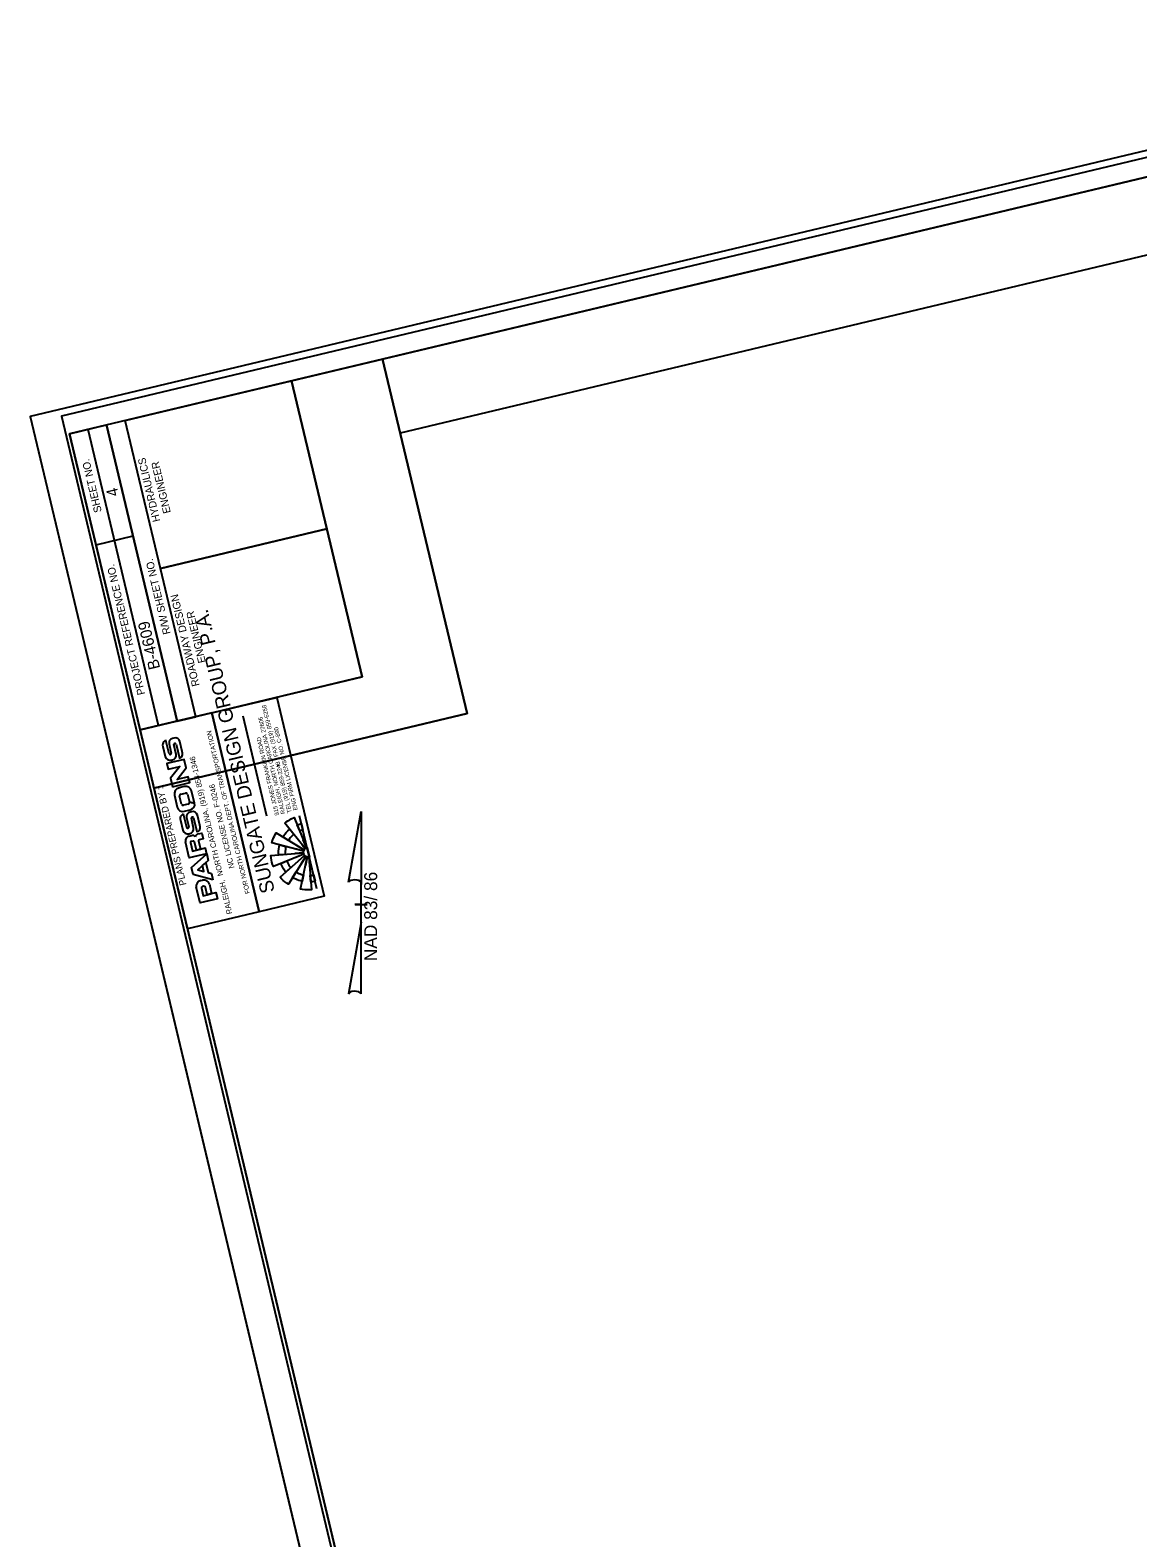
# Model space of a CAD drawing. Extents: x 1735488 to 1736943, y 699358 to 701250.
# Drawn here: x 1735488 to 1736215, y 700259 to 701250 of the extents above; entities that cross this region are included whole.
import ezdxf

# ---------------------------------------------------------------- set-up
doc = ezdxf.new("R2010")
doc.units = 0
for name, color, linetype in [('Default', 7, 'Continuous'), ('Old_Level_2', 7, 'Continuous'), ('Prop North Arrow NAD83 for Plan Sheets CELL', 7, 'Continuous'), ('Sheet Clip Boundary CELL', 7, 'Continuous'), ('Sheet Cutting Line CELL', 7, 'Continuous'), ('Sheet Data Field CELL', 7, 'Continuous'), ('Sheet Layout Plan Border', 7, 'Continuous'), ('Sheet Plan CELL', 7, 'Continuous'), ('Sheet Plan Layout CELL', 7, 'Continuous'), ('Sheet Plot Border Inside CELL', 7, 'Continuous'), ('Sheet Plot Border Outside CELL', 7, 'Continuous')]:
    doc.layers.add(name, color=color, linetype=linetype)

msp = doc.modelspace()

# ---------------------------------------------------------------- linework, layer by layer
at = {"layer": 'Default'}
for p, q in [((1735643.19, 700733.5), (1735627.54, 700799.17)), ((1735676.1, 700685.63), (1735664.66, 700733.63)), ((1735668.39, 700712.12), (1735664.87, 700716.53)), ((1735666.35, 700714.67), (1735668.39, 700712.12)), ((1735669.2, 700712.59), (1735667.09, 700717.83)), ((1735655.66, 700713.45), (1735655.66, 700713.45)), ((1735667.2, 700709.35), (1735661.58, 700708.86)), ((1735667.3, 700710.43), (1735661.83, 700711.86)), ((1735667.42, 700708.44), (1735662.18, 700706.34)), ((1735662.83, 700714.23), (1735667.66, 700711.29)), ((1735667.99, 700707.52), (1735663.75, 700703.78)), ((1735665.72, 700702.12), (1735668.7, 700706.92)), ((1735669.73, 700706.51), (1735668.58, 700700.98)), ((1735670.66, 700706.45), (1735671.14, 700700.83)), ((1735658.96, 700699.63), (1735658.96, 700699.63)), ((1735668.88, 700702.49), (1735668.88, 700702.49)), ((1735671.9, 700692.25), (1735671.9, 700692.25))]:
    msp.add_line(p, q, dxfattribs=at)
for points in [[(1735638.12, 700670.55), (1735606.96, 700801.29), (1735649.78, 700811.49), (1735680.94, 700680.75)], [(1735653.73, 700719.77), (1735654.35, 700720.73), (1735655.06, 700721.69), (1735655.83, 700722.6), (1735656.96, 700723.77), (1735658.22, 700724.86), (1735660.92, 700721.49), (1735660.09, 700720.78), (1735659.19, 700719.88), (1735658.58, 700719.17), (1735658.07, 700718.49), (1735657.42, 700717.52)], [(1735668.41, 700712.12), (1735654.99, 700728.92), (1735655.89, 700729.6), (1735656.97, 700730.35), (1735658.24, 700731.11), (1735659.26, 700731.66), (1735661.2, 700732.54), (1735669.2, 700712.59)], [(1735663.13, 700727.72), (1735664.53, 700728.22), (1735665.82, 700728.58), (1735666.86, 700724.38), (1735665.8, 700724.09), (1735664.74, 700723.71)], [(1735667.3, 700710.43), (1735646.5, 700715.85), (1735646.96, 700717.41), (1735647.63, 700719.18), (1735648.14, 700720.32), (1735648.69, 700721.4), (1735649.31, 700722.47), (1735667.66, 700711.29)], [(1735650.96, 700707.93), (1735650.89, 700709.13), (1735650.9, 700710.49), (1735651.02, 700711.88), (1735651.21, 700713.16), (1735651.51, 700714.54), (1735655.7, 700713.45), (1735655.52, 700712.67), (1735655.34, 700711.65), (1735655.22, 700710.22), (1735655.21, 700709.23), (1735655.27, 700708.31)], [(1735667.42, 700708.44), (1735647.47, 700700.45), (1735646.99, 700701.74), (1735646.55, 700703.21), (1735646.24, 700704.47), (1735645.96, 700706.03), (1735645.79, 700707.48), (1735667.2, 700709.35)], [(1735668.7, 700706.92), (1735657.36, 700688.66), (1735656.2, 700689.43), (1735655.01, 700690.32), (1735653.93, 700691.23), (1735652.84, 700692.27), (1735651.87, 700693.31), (1735667.99, 700707.52)], [(1735670.66, 700706.45), (1735672.53, 700685.05), (1735671.22, 700684.97), (1735669.29, 700684.98), (1735668.09, 700685.06), (1735666.54, 700685.25), (1735665.36, 700685.47), (1735669.73, 700706.51)], [(1735671.12, 700706.53), (1735670.88, 700706.48), (1735670.66, 700706.45), (1735670.15, 700706.45), (1735669.73, 700706.51), (1735669.41, 700706.59), (1735669.12, 700706.7), (1735668.88, 700706.82), (1735668.7, 700706.92), (1735668.31, 700707.2), (1735667.99, 700707.52), (1735667.8, 700707.75), (1735667.63, 700708.02), (1735667.5, 700708.26), (1735667.42, 700708.44), (1735667.28, 700708.9), (1735667.2, 700709.35), (1735667.19, 700709.63), (1735667.2, 700709.87), (1735667.23, 700710.14), (1735667.3, 700710.43), (1735667.44, 700710.87), (1735667.66, 700711.29), (1735667.8, 700711.5), (1735667.98, 700711.73), (1735668.15, 700711.91), (1735668.39, 700712.12), (1735668.8, 700712.4), (1735669.2, 700712.59), (1735669.42, 700712.67), (1735669.64, 700712.73)], [(1735655.76, 700696.73), (1735655.09, 700697.53), (1735654.19, 700698.77), (1735653.35, 700700.13), (1735652.71, 700701.39), (1735652.28, 700702.38), (1735656.3, 700703.99), (1735656.71, 700703.05), (1735657.16, 700702.18), (1735657.7, 700701.3), (1735658.34, 700700.39), (1735659, 700699.59)], [(1735666.42, 700690.54), (1735665.23, 700690.83), (1735664.29, 700691.11), (1735663.18, 700691.51), (1735662.19, 700691.94), (1735661.2, 700692.43), (1735660.1, 700693.07), (1735662.38, 700696.74), (1735663.3, 700696.21), (1735664.11, 700695.81), (1735664.96, 700695.46), (1735665.9, 700695.13), (1735666.65, 700694.92), (1735667.3, 700694.77)], [(1735674.9, 700690.67), (1735674.07, 700690.49), (1735673.09, 700690.33), (1735672.08, 700690.21), (1735671.7, 700694.52), (1735672.43, 700694.6), (1735673.16, 700694.72), (1735673.89, 700694.88)]]:
    msp.add_lwpolyline(points, close=True, dxfattribs=at)
for start, end in [(103.40586, 283.40586), (283.40586, 103.40586)]:
    msp.add_arc((1735650.54, 700766.89), 0.138, start, end, dxfattribs=at)
at = {"layer": 'Old_Level_2'}
for p, q in [((1735606.96, 700801.29), (1735559.86, 700790.06)), ((1735606.96, 700801.29), (1735638.12, 700670.55)), ((1735591.02, 700659.32), (1735559.86, 700790.06)), ((1735582.13, 700784.73), (1735581.24, 700784.52)), ((1735574.81, 700779.17), (1735576.35, 700772.7)), ((1735579, 700774.44), (1735576.91, 700783.2)), ((1735578.92, 700781.03), (1735580.41, 700774.77)), ((1735583.52, 700773.98), (1735582.14, 700780.4)), ((1735587.63, 700775.83), (1735586.04, 700782.51)), ((1735580.62, 700770.27), (1735581.07, 700770.38)), ((1735582.43, 700747.19), (1735584.32, 700739.27)), ((1735588.88, 700752.8), (1735585.67, 700752.03)), ((1735587.03, 700741.37), (1735585.8, 700746.53)), ((1735586.73, 700747.92), (1735589.63, 700748.61)), ((1735595.73, 700741.85), (1735593.78, 700750.04)), ((1735590.54, 700726.03), (1735588.45, 700734.79)), ((1735591.39, 700741.25), (1735588.49, 700740.55)), ((1735589.03, 700736.62), (1735592.83, 700737.52)), ((1735595.73, 700741.85), (1735592.32, 700742.63)), ((1735593.67, 700736.33), (1735592.77, 700736.11)), ((1735586.34, 700730.77), (1735587.89, 700724.3)), ((1735590.46, 700732.62), (1735591.95, 700726.37)), ((1735595.06, 700725.58), (1735593.67, 700732)), ((1735599.17, 700727.43), (1735597.58, 700734.11)), ((1735592.16, 700721.87), (1735592.61, 700721.98)), ((1735592.2, 700720.36), (1735593.92, 700720.77)), ((1735594.72, 700717.06), (1735593.45, 700716.76)), ((1735599.73, 700691.11), (1735600.84, 700691.37)), ((1735601.56, 700687.35), (1735600.89, 700687.19)), ((1735638.12, 700670.55), (1735591.02, 700659.32))]:
    msp.add_line(p, q, dxfattribs=at)
for points in [[(1735583.55, 700780.74), (1735585.72, 700771.63), (1735585.95, 700771.68)], [(1735591.09, 700747.79), (1735592.32, 700742.63), (1735595.73, 700741.85), (1735593.78, 700750.04)], [(1735595.09, 700732.33), (1735597.26, 700723.23), (1735597.48, 700723.28)], [(1735593.05, 700716.15), (1735594.39, 700710.52), (1735596.92, 700711.12), (1735599.68, 700711.78), (1735602.72, 700712.51), (1735603.62, 700708.75), (1735592.24, 700706.04), (1735589.72, 700716.6)], [(1735597.93, 700721.72), (1735600.39, 700722.31), (1735601.3, 700718.49), (1735598.69, 700717.86), (1735598.37, 700717.27), (1735599.68, 700711.78), (1735596.92, 700711.12), (1735595.63, 700716.54)], [(1735600.2, 700686.14), (1735601.39, 700681.12), (1735604, 700681.74), (1735606.89, 700682.5), (1735609.72, 700683.17), (1735610.68, 700679.13), (1735599.3, 700676.42), (1735596.84, 700686.74)], [(1735605.4, 700688.78), (1735606.89, 700682.5), (1735604, 700681.74), (1735602.84, 700686.62)]]:
    msp.add_lwpolyline(points, dxfattribs=at)
for points in [[(1735581.1, 700752.78), (1735592.48, 700755.49), (1735591.56, 700759.35), (1735584.19, 700757.59), (1735590.15, 700765.27), (1735588.85, 700770.71), (1735577.47, 700767.99), (1735578.36, 700764.28), (1735585.94, 700766.09), (1735579.78, 700758.29)], [(1735607.7, 700691.63), (1735594.83, 700695.18), (1735593.74, 700699.72), (1735603.65, 700708.63), (1735604.67, 700704.36), (1735597.74, 700698.13), (1735601.86, 700697), (1735600.91, 700700.99), (1735602.98, 700702.86), (1735604.54, 700696.33), (1735606.72, 700695.76)]]:
    msp.add_lwpolyline(points, close=True, dxfattribs=at)
for centre, major_axis, ratio, start_param, end_param in [((1735581.9, 700781.74), (-2.98, -0.71), 0.934072, 4.712389, 6.283185), ((1735582.84, 700781.75), (-3.2, -0.76), 0.934072, 3.141593, 4.712389), ((1735579.64, 700780.32), (-4.84, -1.15), 0.934072, 5.902203, 6.283185), ((1735577.62, 700780.57), (-2.83, -0.67), 0.934072, 4.738699, 5.901866), ((1735579.71, 700774.61), (-0.707, -0.169), 0.934072, 0, 3.141593), ((1735580.38, 700773.3), (3.13, 0.75), 0.934072, 4.712389, 6.260753), ((1735582.85, 700780.57), (-0.707, -0.169), 0.934072, 3.141593, 6.283185), ((1735580.19, 700774.06), (-7.44, -1.77), 0.934072, 2.847261, 3.141593), ((1735579.84, 700773.54), (-3.5, -0.83), 0.934072, 0, 1.570796), ((1735585.43, 700773.84), (2.31, 0.55), 0.934072, 4.712389, 5.988639), ((1735586.6, 700748.18), (-4.17, -0.99), 0.924824, 4.712389, 6.283185), ((1735587, 700746.82), (-1.19, -0.28), 0.924824, 4.712389, 6.283185), ((1735589.76, 700749.08), (-4.02, -0.96), 0.924824, 3.141593, 4.712389), ((1735589.9, 700747.51), (-1.19, -0.28), 0.924824, 3.141593, 4.712389), ((1735588.18, 700740.19), (-3.87, -0.92), 0.924824, 0, 1.570796), ((1735589.15, 700732.17), (-2.83, -0.67), 0.934072, 4.738699, 5.901866), ((1735588.23, 700741.66), (1.19, 0.28), 0.924824, 3.141593, 4.712389), ((1735593.44, 700733.34), (-2.98, -0.71), 0.934072, 4.712389, 6.283185), ((1735591.13, 700742.35), (1.19, 0.28), 0.924824, 4.712389, 6.283185), ((1735592.01, 700740.96), (3.72, 0.89), 0.924824, 4.712389, 6.283185), ((1735594.38, 700733.34), (-3.2, -0.76), 0.934072, 3.141593, 4.712389), ((1735591.18, 700731.92), (-4.84, -1.15), 0.934072, 5.902203, 6.283185), ((1735591.24, 700726.2), (-0.707, -0.169), 0.934072, 0, 3.141593), ((1735591.92, 700724.9), (3.13, 0.75), 0.934072, 4.712389, 6.260753), ((1735594.38, 700732.17), (-0.707, -0.169), 0.934072, 3.141593, 6.283185), ((1735596.97, 700725.44), (2.31, 0.55), 0.934072, 4.712389, 5.988639), ((1735591.73, 700725.66), (-7.44, -1.77), 0.934072, 2.847261, 3.141593), ((1735591.38, 700725.13), (-3.5, -0.83), 0.934072, 0, 1.570796), ((1735592.92, 700717.37), (-3.2, -0.76), 0.934072, 4.712389, 6.283185), ((1735593.57, 700716.27), (-0.521, -0.124), 0.934072, 4.712389, 6.283185), ((1735594.35, 700718.96), (-1.93, -0.46), 0.934072, 3.34512, 4.712389), ((1735594.89, 700716.37), (-0.744, -0.177), 0.934072, 3.141593, 4.712389), ((1735598.43, 700719.64), (-2.23, -0.53), 0.934072, 4.712389, 5.969561), ((1735600.56, 700687.62), (-3.72, -0.89), 0.93676, 4.712389, 6.283185), ((1735601.1, 700686.35), (-0.893, -0.213), 0.93676, 4.712389, 6.283185), ((1735601.67, 700687.89), (-3.72, -0.89), 0.93676, 3.141593, 4.712389), ((1735601.8, 700686.37), (-1.04, -0.25), 0.93676, 3.141593, 4.712389)]:
    msp.add_ellipse(centre, major_axis=major_axis, ratio=ratio, start_param=start_param, end_param=end_param, dxfattribs=at)
at = {"layer": 'Prop North Arrow NAD83 for Plan Sheets CELL'}
for p, q in [((1735696.88, 700690.07), (1735705.1, 700736.41)), ((1735705.15, 700736.41), (1735705.1, 700736.41)), ((1735705.15, 700736.41), (1735705.1, 700736.41)), ((1735705.15, 700736.41), (1735705.13, 700688.61)), ((1735705.12, 700663.81), (1735705.13, 700690.01)), ((1735705.13, 700688.61), (1735705.13, 700689.96)), ((1735701.12, 700675.42), (1735701.07, 700675.42)), ((1735704.67, 700675.42), (1735701.12, 700675.42)), ((1735701.17, 700675.42), (1735709.17, 700675.41)), ((1735705.12, 700663.81), (1735696.75, 700616.57)), ((1735705.15, 700616.76), (1735705.12, 700663.81))]:
    msp.add_line(p, q, dxfattribs=at)
for centre, start_param, end_param in [((1735701.02, 700689.57), 0.216388, 2.908219), ((1735700.99, 700616.4), 0.201328, 3.141593)]:
    msp.add_ellipse(centre, major_axis=(4.23, -0.03), ratio=0.461098, start_param=start_param, end_param=end_param, dxfattribs=at)
at = {"layer": 'Sheet Clip Boundary CELL'}
msp.add_lwpolyline([(1736871.06, 699817.6), (1736546.47, 701179.46), (1735730.8, 700985.06), (1735774.68, 700800.95), (1735568.96, 700751.92), (1735849.67, 699574.16)], close=True, dxfattribs=at)
at = {"layer": 'Sheet Cutting Line CELL'}
msp.add_line((1735487.67, 700995.98), (1735877.99, 699358.36), dxfattribs=at)
at = {"layer": 'Sheet Layout Plan Border'}
msp.add_lwpolyline([(1736871.06, 699817.6), (1736546.47, 701179.46), (1735730.8, 700985.06), (1735774.68, 700800.95), (1735568.96, 700751.92), (1735849.67, 699574.16)], close=True, dxfattribs=at)
at = {"layer": 'Sheet Plan CELL'}
for p, q in [((1735572.07, 700792.96), (1735525.7, 700987.56)), ((1735584.26, 700795.88), (1735537.86, 700990.46)), ((1735584.26, 700795.88), (1735537.86, 700990.46)), ((1735530.94, 700911.68), (1735555.25, 700917.53)), ((1735573.21, 700896.09), (1735682.61, 700922.18)), ((1735584.26, 700795.88), (1735596.41, 700798.77))]:
    msp.add_line(p, q, dxfattribs=at)
for points in [[(1735513.48, 700984.69), (1735861.26, 699525.52), (1736882.65, 699768.96), (1736534.88, 701228.1)], [(1736882.65, 699768.96), (1735861.29, 699525.5), (1735559.86, 700790.06), (1735705.83, 700824.86), (1735659.46, 701019.45), (1736534.88, 701228.1)], [(1735573.21, 700896.09), (1735550.02, 700993.35), (1735659.46, 701019.45), (1735682.66, 700922.18)], [(1735559.86, 700790.06), (1735513.48, 700984.69), (1735537.86, 700990.46), (1735584.26, 700795.88)], [(1735596.41, 700798.77), (1735573.21, 700896.09), (1735682.66, 700922.18), (1735705.83, 700824.86)]]:
    msp.add_lwpolyline(points, close=True, dxfattribs=at)
at = {"layer": 'Sheet Plan Layout CELL'}
for points in [[(1735861.29, 699525.5), (1736882.65, 699768.96), (1736534.88, 701228.09), (1735719.21, 701033.68), (1735774.68, 700800.95), (1735568.96, 700751.92)], [(1735774.68, 700800.95), (1735719.21, 701033.71), (1735513.48, 700984.7), (1735568.96, 700751.92)]]:
    msp.add_lwpolyline(points, close=True, dxfattribs=at)
at = {"layer": 'Sheet Plot Border Inside CELL'}
msp.add_lwpolyline([(1736920.68, 699620.24), (1736534.41, 701240.83), (1735508.17, 700996.24), (1735894.43, 699375.64)], close=True, dxfattribs=at)
at = {"layer": 'Sheet Plot Border Outside CELL'}
msp.add_lwpolyline([(1736943.15, 699612.23), (1736552.83, 701249.86), (1735487.67, 700995.98), (1735877.99, 699358.36)], close=True, dxfattribs=at)

# ---------------------------------------------------------------- texts
at = {"layer": 'Default'}
for s, height, p in [('SUNGATE DESIGN GROUP, P.A.', 9.3194, (1735648.47, 700684.01)), ('TEL (919) 859-2243   FAX (919) 859-6258', 2.8007, (1735659.49, 700735.87)), ('RALEIGH, NORTH CAROLINA 27606', 2.8007, (1735655.29, 700735.16)), ('ENG FIRM LICENSE NO. C-890', 2.8007, (1735663.44, 700737.61)), ('915 JONES FRANKLIN ROAD', 2.8007, (1735651.28, 700734.2))]:
    msp.add_text(s, height=height, rotation=103.40586, dxfattribs=at).set_placement(p)
at = {"layer": 'Old_Level_2'}
for s, height, rotation, p in [('FOR NORTH CAROLINA DEPT. OF TRANSPORTATION', 3.1013, 103.40586, (1735632.1, 700682.78)), ('RALEIGH,  NORTH CAROLINA, (919) 854-1346', 3.5754, 103.40588, (1735620.47, 700669.44)), ('PLANS PREPARED BY : ', 4.4145, 103.40496, (1735590.36, 700688.43)), ('NC LICENSE NO. F-0246', 3.5754, 103.40588, (1735621.85, 700699.52))]:
    msp.add_text(s, height=height, rotation=rotation, dxfattribs=at).set_placement(p)
at = {"layer": 'Prop North Arrow NAD83 for Plan Sheets CELL'}
msp.add_text('NAD 83/ 86', height=8.5, rotation=89.97606, dxfattribs=at).set_placement((1735715.63, 700638.12))
at = {"layer": 'Sheet Data Field CELL'}
for s, p in [('4  ', (1735545.96, 700944.37)), ('B-4609   ', (1735573.12, 700830.69))]:
    msp.add_text(s, height=7.5, rotation=103.40592, dxfattribs=at).set_placement(p)
at = {"layer": 'Sheet Plan CELL'}
for s, height, p in [('SHEET NO.', 5, (1735534.75, 700933.51)), ('HYDRAULICS', 5, (1735573.22, 700927.41)), ('ENGINEER', 5, (1735580.1, 700932.92)), ('PROJECT REFERENCE NO.', 5.0001, (1735563.2, 700813.68)), ('R/W SHEET NO.', 5.0001, (1735579.98, 700853.45)), ('ROADWAY DESIGN', 5.0001, (1735599.02, 700819.31)), ('ENGINEER', 5, (1735603.11, 700834.66))]:
    msp.add_text(s, height=height, rotation=103.40592, dxfattribs=at).set_placement(p)

doc.saveas('drawing.dxf')
